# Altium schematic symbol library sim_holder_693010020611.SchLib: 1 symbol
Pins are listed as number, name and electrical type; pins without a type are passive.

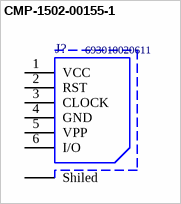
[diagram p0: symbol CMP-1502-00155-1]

## CMP-1502-00155-1
designator J?, comment 693010020611
WR-CRD Mini SIM Card Connector Header Shielded; Manufacturer: Wurth Elektronik; Working Voltage: 50VAC; Rated Current: 0.5A; Withstanding Voltage: 500VAC
footprint 693010020611 (SIM CARD CONNECTOR HEADER SHIELD ED 6PINS)
pins: 1 VCC, 2 RST, 3 CLOCK, 4 GND, 5 VPP, 6 I/O, Shiled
